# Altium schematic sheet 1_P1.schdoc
size 307 x 218 mm; Symbol: Drawing-Symbol_A4; Device: Drawing-Symbol_A4; Company: 嘉立创EDA; Version: V1.0; Page Size: A4; @Project Name: HDMI2CSI; @Page Count: 1; @Update Date: 2025-08-17; @Create Date: 2025-08-17; @Schematic Name: Schematic1; @Page No: 1; @Page Name: P1; @Create Time: 03:15:43; @Update Time: 03:17:25; Width: 1170; Height: 825; Region Start: 1; X Region Count: 6; Y Region Count: 4; Blade Width: 10; Title Block Position: 3; @Board Name: Board1
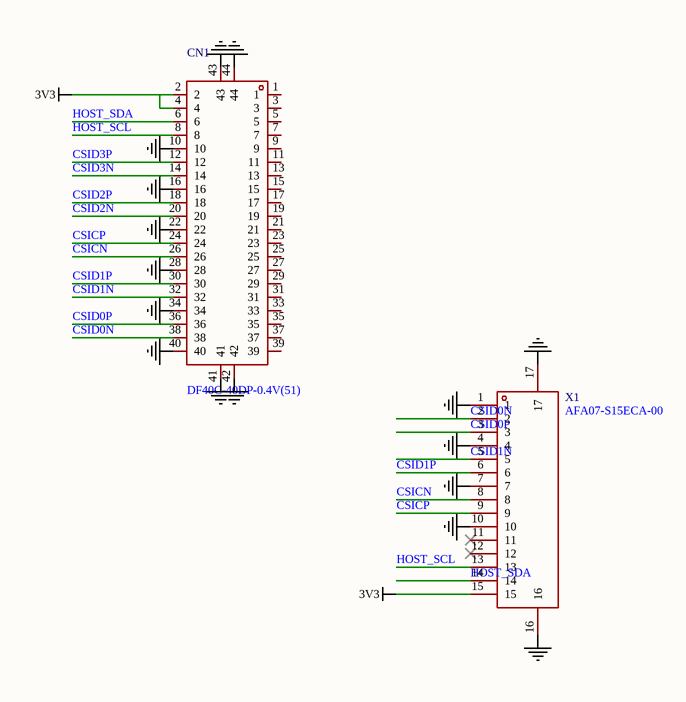
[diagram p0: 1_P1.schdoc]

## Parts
CN1  DF40C-40DP-0.4V(51)  [CONN-SMD_DF40C-40DP-0.4V]
X1  AFA07-S15ECA-00  [FPC-SMD_15P-P1.00_JS_AFA07-S15XXX]

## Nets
3V3: CN1.2 CN1.4 X1.15
GND: CN1.10 CN1.16 CN1.22 CN1.28 CN1.34 CN1.40 CN1.41 CN1.42 CN1.43 CN1.44 X1.1 X1.4 X1.7 X1.10 X1.16 X1.17
CSICN: CN1.26 X1.8
CSICP: CN1.24 X1.9
CSID0N: CN1.38 X1.2
CSID0P: CN1.36 X1.3
CSID1N: CN1.32 X1.5
CSID1P: CN1.30 X1.6
CSID2N: CN1.20
CSID2P: CN1.18
CSID3N: CN1.14
CSID3P: CN1.12
HOST_SCL: CN1.8 X1.13
HOST_SDA: CN1.6 X1.14

Not connected (* = marked no-connect by the designer): CN1 1 3 5 7 9 11 13 15 17 19 21 23 25 27 29 31 33 35 37 39; X1 11* 12*

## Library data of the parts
CN1 = DF40C-40DP-0.4V(51): Manufacturer: HRS(广濑); Add into BOM: yes; Pitch: 0.4mm; Current Rating (Max): 300mA
X1 = AFA07-S15ECA-00: Manufacturer: JS(钜硕电子); Add into BOM: yes; Locking Feature: 抽屉式; Number of Contacts: 15P; Pitch: 1mm; FFC, FCB Thickness: 0.3mm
